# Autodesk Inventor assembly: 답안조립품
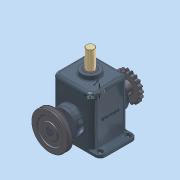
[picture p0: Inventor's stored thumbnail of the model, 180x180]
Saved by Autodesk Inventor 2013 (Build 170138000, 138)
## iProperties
Created: 2015-03
Part Number: 답안조립품
Document SubType Name: Assembly
Designer: Administrator
Mass: 8579.28 g
Surface Area: 4386.42 cm^2
Volume: 1982.54 cm^3
Density: 4.32742 g/cm^3
Author: Administrator
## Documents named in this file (15)
- C:\Documents and Settings\Administrator\바탕 화면\350305V1019\답안조립품.iam
- C:\Documents and Settings\Administrator\바탕 화면\350305V1019\본체.ipt
- C:\Documents and Settings\Administrator\바탕 화면\350305V1019\베어링 6205.ipt
- C:\Documents and Settings\Administrator\바탕 화면\350305V1019\커버.ipt
- C:\Documents and Settings\Administrator\바탕 화면\350305V1019\오일실.ipt
- C:\Documents and Settings\Administrator\바탕 화면\350305V1019\M4x0.5.ipt
- C:\Documents and Settings\Administrator\바탕 화면\350305V1019\편심축.ipt
- C:\Documents and Settings\Administrator\바탕 화면\350305V1019\체인 스프로킷.ipt
- C:\Documents and Settings\Administrator\바탕 화면\350305V1019\키 8x8.ipt
- C:\Documents and Settings\Administrator\바탕 화면\350305V1019\멈춤나사 M5x0.5.ipt
- C:\Documents and Settings\Administrator\바탕 화면\350305V1019\멈춤링.ipt
- C:\Documents and Settings\Administrator\바탕 화면\350305V1019\V-벨트풀리.ipt
- C:\Documents and Settings\Administrator\바탕 화면\350305V1019\부시.ipt
- C:\Documents and Settings\Administrator\바탕 화면\350305V1019\슬라이드.ipt
- C:\Documents and Settings\Administrator\바탕 화면\350305V1019\7-가변스프링.ipt
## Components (9 placed, 4 different names)
1. 5-체인 스프로킷:1 — 플러쉬:2, 각도:2
2. V-벨트풀리:1 — 플러쉬:4, 각도:4, 구속조건
3. 7-가변스프링:1
4. M4x0.5:1
5. M4x0.5:2
6. M4x0.5:3
7. M4x0.5:4
8. M4x0.5:5
9. M4x0.5:6
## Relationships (5: Angle 3, Flush 2)
- 플러쉬:2 [Flush]: 5-체인 스프로킷:1
- 각도:2 [Angle]: 5-체인 스프로킷:1
- 플러쉬:4 [Flush]: V-벨트풀리:1
- 각도:4 [Angle]: V-벨트풀리:1
- 구속조건 [Angle]: V-벨트풀리:1
